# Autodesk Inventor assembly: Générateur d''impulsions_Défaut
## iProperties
Shininess: 64.0
Length Units: 11269
Angle Units: 11279
Time Units: 11290
Mass Units: 11283
Length Display Precision: 3
Angle Display Precision: 2
Compacted: True
Created: 2006-01
Part Number: Générateur d''impulsions_Défaut
Document SubType Name: Assembly
Designer: riri
Density: 0.0
Volumn: 0.0
Area: 0.0
PropertySet Name: Model Information
Control State: 0
Master: False
Checked Out: False
Author: riri
